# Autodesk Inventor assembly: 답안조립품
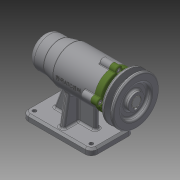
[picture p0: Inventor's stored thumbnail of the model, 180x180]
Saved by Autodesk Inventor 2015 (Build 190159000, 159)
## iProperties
Created: 2019-07
Part Number: 답안조립품
Document SubType Name: Assembly
Designer: now
Author: now
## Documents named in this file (12)
- C:\Users\now\Desktop\490704V1029\답안조립품.iam
- C:\Users\now\Desktop\490704V1029\V벨트풀리.ipt
- C:\Users\now\Desktop\490704V1029\멈춤나사 M3.ipt
- C:\Users\now\Desktop\490704V1029\베어링 6004.ipt
- C:\Users\now\Desktop\490704V1029\베어링 51202.ipt
- C:\Users\now\Desktop\490704V1029\본체.ipt
- C:\Users\now\Desktop\490704V1029\볼트 M4.ipt
- C:\Users\now\Desktop\490704V1029\어댑터슬리브.ipt
- C:\Users\now\Desktop\490704V1029\오일 실.ipt
- C:\Users\now\Desktop\490704V1029\축.ipt
- C:\Users\now\Desktop\490704V1029\커버.ipt
- C:\Users\now\Desktop\490704V1029\키 5 x 5 x 16.ipt
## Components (1 placed, 1 different names)
1. V벨트풀리:1
